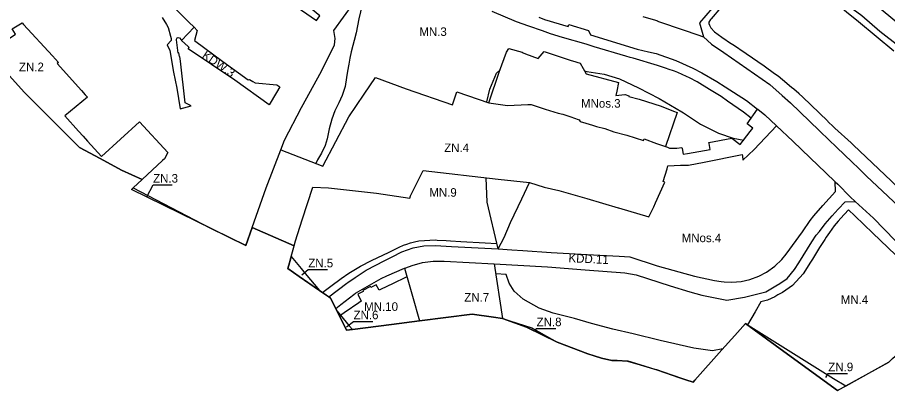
# Model space of a CAD drawing. Extents: x 7420436 to 7421695, y 5547261 to 5547909.
# Drawn here: x 7420752 to 7421258, y 5547294 to 5547511 of the extents above; entities that cross this region are included whole.
import ezdxf

# ---------------------------------------------------------------- set-up
doc = ezdxf.new("R2010")
doc.units = 0
for name, color, linetype in [('LIN_Granica Planu', 7, 'Continuous'), ('LIN_linie_rozgraniczajace', 7, 'Continuous'), ('LIN_nieprzekraczalna linia zabudowy', 7, 'Continuous'), ('TXT_Oznaczenia_przeznaczen', 7, 'Continuous')]:
    doc.layers.add(name, color=color, linetype=linetype)

msp = doc.modelspace()

# ---------------------------------------------------------------- linework, layer by layer
at = {"layer": 'LIN_Granica Planu'}
msp.add_lwpolyline([(7421259.05, 5547310.22), (7421233.98, 5547296.24), (7421229.23, 5547293.56), (7421198, 5547316.43), (7421175.73, 5547332.73), (7421175.66, 5547332.65), (7421169.4, 5547325.72), (7421161.85, 5547317.24), (7421146.1, 5547299.57), (7421145.17, 5547298.52), (7421140.86, 5547299.92), (7421136.27, 5547301.4), (7421135.97, 5547301.5), (7421132.96, 5547302.49), (7421124.07, 5547305.62), (7421123.66, 5547305.75), (7421114.38, 5547308.61), (7421107.35, 5547310.66), (7421106.92, 5547310.78), (7421100.9, 5547311.01), (7421097.82, 5547311.2), (7421091.82, 5547312.48), (7421087.65, 5547313.76), (7421083.89, 5547314.92), (7421066.03, 5547321.79), (7421048.25, 5547330.61), (7421034.16, 5547335.53), (7421028.95, 5547336.31), (7421016.64, 5547338.14), (7420985.93, 5547334.23), (7420969.62, 5547332.15), (7420946.83, 5547329.24), (7420943.45, 5547328.81), (7420934.09, 5547347.5), (7420915.94, 5547360.1), (7420909.33, 5547364.68), (7420910.25, 5547368.04), (7420910.46, 5547368.84), (7420912.94, 5547377.91), (7420888.52, 5547388.6), (7420884.81, 5547378.13), (7420818.18, 5547410.75), (7420818.2, 5547410.77), (7420819.17, 5547411.67), (7420824.52, 5547416.62), (7420812.48, 5547421.89), (7420799.97, 5547428.69), (7420788.05, 5547435.17), (7420777.16, 5547446), (7420755.7, 5547467.33), (7420734.75, 5547490.49)], dxfattribs=at)
at = {"layer": 'LIN_linie_rozgraniczajace'}
for p, q in [((7420847.46, 5547497.47), (7420854.67, 5547505.22)), ((7420841.44, 5547497.57), (7420838.99, 5547495.05))]:
    msp.add_line(p, q, dxfattribs=at)
for points in [[(7420787.58, 5547570.94), (7420802.56, 5547555.9), (7420812.54, 5547546.41), (7420823.13, 5547536.3), (7420842.51, 5547517.12), (7420845.49, 5547514.43), (7420851.66, 5547508.17), (7420854.67, 5547505.22), (7420856.54, 5547503.41), (7420855, 5547497.57)], [(7421190.81, 5547554.87), (7421207.78, 5547540.57), (7421229.97, 5547522.26), (7421236.25, 5547517.3), (7421243.31, 5547512.03), (7421253.86, 5547503.01), (7421265.16, 5547494.28), (7421275.34, 5547485.4), (7421281.23, 5547492.23), (7421278.94, 5547493.96), (7421270.78, 5547500.63), (7421271.58, 5547501.53), (7421250.27, 5547519.26), (7421237.97, 5547529.35), (7421228.01, 5547538.07), (7421207.81, 5547554.72), (7421197.34, 5547562.82)], [(7420898.71, 5547553.16), (7420881.83, 5547531.98), (7420878.15, 5547527.69), (7420880.42, 5547525.69), (7420882.59, 5547523.78), (7420890.6, 5547533.64), (7420911.68, 5547519.04), (7420925.95, 5547509.07), (7420927.93, 5547511.91), (7420922.47, 5547516.42), (7420897.75, 5547533.39), (7420908.28, 5547548.05)], [(7421190.81, 5547554.87), (7421189.2, 5547554.66), (7421179.25, 5547543.26), (7421170.41, 5547532.52), (7421158.61, 5547518.98), (7421156.23, 5547516.25), (7421148.93, 5547507.87), (7421151.31, 5547499.61)], [(7420905.23, 5547433.9), (7420907.37, 5547439.48), (7420917.18, 5547458.56), (7420928.84, 5547479.65), (7420936.4, 5547494.95), (7420936.88, 5547498.7), (7420936.09, 5547503.36), (7420952.92, 5547526.84), (7420943.47, 5547533.91), (7420933.81, 5547540.07), (7420930.16, 5547533.19), (7420908.28, 5547548.05)], [(7420734.75, 5547490.49), (7420750.75, 5547501.15), (7420748.84, 5547504.29), (7420754.54, 5547507.89), (7420755.44, 5547506.92), (7420772.24, 5547488.5), (7420775.71, 5547484.7), (7420775.06, 5547484.17), (7420789.09, 5547468.39), (7420791.36, 5547465.83), (7420792.6, 5547464.43), (7420779.43, 5547453.65), (7420787.41, 5547444.79), (7420790.03, 5547441.87), (7420792.67, 5547438.95), (7420800.8, 5547429.93), (7420822.96, 5547450.1), (7420839.32, 5547432.31), (7420837.5, 5547428.63), (7420836.4, 5547427.61), (7420824.52, 5547416.62)], [(7420836.09, 5547510.97), (7420838.59, 5547506.92), (7420839.62, 5547505.05), (7420841.03, 5547500.09), (7420841.31, 5547498.74), (7420841.44, 5547497.57)], [(7421055.34, 5547511.13), (7421058.67, 5547509.73), (7421072.49, 5547505.61), (7421072.88, 5547506.9), (7421084.35, 5547503.33), (7421085.41, 5547500.84), (7421112.63, 5547492.54), (7421119.23, 5547490.86), (7421123.62, 5547489.88), (7421135.16, 5547485.78), (7421144.95, 5547481.45), (7421150.2, 5547478.72), (7421159.07, 5547473.63), (7421163.78, 5547470.48), (7421176.31, 5547462.58), (7421182.69, 5547457.56)], [(7421115.89, 5547511.41), (7421123.28, 5547509.27), (7421124.43, 5547508.88), (7421124.49, 5547508.85), (7421139.96, 5547503.52), (7421147.34, 5547500.98), (7421151.31, 5547499.61)], [(7420845.47, 5547490.14), (7420844.43, 5547497.96), (7420844.55, 5547498.3), (7420844.8, 5547499.05), (7420845.5, 5547499.28), (7420846.12, 5547499.05), (7420847.09, 5547497.82), (7420847.46, 5547497.47), (7420851.19, 5547493.93), (7420851.79, 5547493.49)], [(7420855, 5547497.57), (7420871.5, 5547485.33), (7420886.16, 5547474.68), (7420886.9, 5547474.71), (7420888.98, 5547473.57), (7420890.2, 5547472.84), (7420902.88, 5547471.78), (7420904.65, 5547470.6), (7420902.74, 5547467.23), (7420898.43, 5547460.04), (7420878.35, 5547474.33), (7420851.17, 5547492.71), (7420851.79, 5547493.49)], [(7421151.31, 5547499.61), (7421155.87, 5547495.39), (7421163.14, 5547490.46), (7421189.92, 5547471.9), (7421196.95, 5547465.55), (7421201.8, 5547461.13), (7421218.54, 5547445.14), (7421219.16, 5547444.55), (7421228.93, 5547435.23), (7421237.56, 5547426.86), (7421241.59, 5547422.91), (7421246.18, 5547418.57), (7421255.37, 5547409.72), (7421268.45, 5547397.44)], [(7420838.99, 5547495.05), (7420840.64, 5547491.67)], [(7420840.64, 5547491.67), (7420842.63, 5547479.06), (7420844.59, 5547469.77), (7420846.61, 5547457.69), (7420853.07, 5547459.53), (7420849.56, 5547461.17), (7420846.79, 5547485.39), (7420846.46, 5547488.19), (7420846.13, 5547488.18), (7420845.76, 5547490.24), (7420845.47, 5547490.14)], [(7421026.34, 5547461.24), (7421032.51, 5547479.61), (7421036.64, 5547490.66), (7421037.85, 5547492.93), (7421045.6, 5547490.7), (7421046.18, 5547490.38), (7421047.67, 5547489.82), (7421055.05, 5547487.05), (7421058.38, 5547491.19), (7421074.19, 5547485.92), (7421074.88, 5547485.71), (7421079.44, 5547484.34), (7421082.92, 5547478.08), (7421101.83, 5547472.98), (7421100.8, 5547467.97), (7421100.28, 5547465.47), (7421105.37, 5547465.98), (7421105.6, 5547465.98), (7421107.74, 5547465.26), (7421107.67, 5547464.98), (7421113.79, 5547463.33), (7421126.61, 5547459.23), (7421133.77, 5547456.35), (7421135.87, 5547455.51), (7421129.01, 5547435.73)], [(7420734.75, 5547490.49), (7420755.7, 5547467.33), (7420777.16, 5547446), (7420788.05, 5547435.17), (7420799.97, 5547428.69), (7420812.48, 5547421.89), (7420824.52, 5547416.62)], [(7420905.23, 5547433.9), (7420929.58, 5547424.28), (7420944.73, 5547453.06), (7420953.78, 5547466.23), (7420960.29, 5547475.9), (7420978.09, 5547469.36), (7421005.17, 5547460.06), (7421007.68, 5547467.61), (7421026.34, 5547461.24)], [(7421026.34, 5547461.24), (7421037.09, 5547459.62), (7421049.02, 5547460.21), (7421050.96, 5547460.24), (7421059.06, 5547457.58), (7421066.55, 5547455.21), (7421069.31, 5547454.51), (7421074.57, 5547452.91), (7421075.52, 5547452.53), (7421078.9, 5547451.2), (7421079.48, 5547450.34), (7421082.75, 5547449.36), (7421086.67, 5547448.17), (7421088.93, 5547447.42), (7421093.84, 5547446.17), (7421099.1, 5547444.27), (7421106.6, 5547442.36), (7421116.37, 5547439.24), (7421116.73, 5547440.17), (7421123.87, 5547437.48), (7421129.01, 5547435.73)], [(7421129.01, 5547435.73), (7421130.27, 5547435.3), (7421131.39, 5547434.76), (7421135.64, 5547434.7), (7421138.67, 5547435.25), (7421138.78, 5547434.69), (7421139.39, 5547431.28), (7421141.82, 5547431.72), (7421155.11, 5547434.11), (7421154.49, 5547437.52), (7421154.38, 5547438.13), (7421167.78, 5547440.58), (7421172.62, 5547436.87), (7421178.43, 5547444.44), (7421179.91, 5547446.37), (7421176.56, 5547448.96), (7421182.69, 5547457.56)], [(7421182.69, 5547457.56), (7421182.85, 5547457.43), (7421186.83, 5547454.26), (7421193.73, 5547447.75)], [(7421049.85, 5547414.7), (7421058.47, 5547412.06), (7421067.09, 5547410.04), (7421083.33, 5547405.39), (7421101.58, 5547400.1), (7421101.78, 5547399.97), (7421119.32, 5547394.78), (7421122.25, 5547400.66), (7421123.25, 5547402.9), (7421128.74, 5547415.05), (7421127.74, 5547415.47), (7421130.04, 5547422.84), (7421130.51, 5547424.49), (7421137.84, 5547424.94), (7421142.56, 5547424.94), (7421151.69, 5547426.7), (7421173.72, 5547431.04), (7421173.95, 5547430.37), (7421174.04, 5547427.85), (7421180.74, 5547434.1), (7421193.73, 5547447.75)], [(7421193.73, 5547447.75), (7421203.24, 5547438.78), (7421213.3, 5547429.18), (7421222.49, 5547420.38), (7421227.8, 5547415.25)], [(7420888.52, 5547388.6), (7420896.73, 5547411.77), (7420905.23, 5547433.9)], [(7420912.94, 5547377.91), (7420913.71, 5547380.74), (7420917.66, 5547393), (7420923.84, 5547412.16), (7420932.97, 5547411.71), (7420960.92, 5547408.53), (7420980.25, 5547405.76), (7420980.75, 5547407.07), (7420987.98, 5547421.73), (7421031.7, 5547416.76), (7421049.85, 5547414.7)], [(7420819.17, 5547411.67), (7420824.52, 5547416.62), (7420824.52, 5547416.62)], [(7420863.54, 5547388.54), (7420818.18, 5547410.75), (7420818.2, 5547410.77), (7420819.17, 5547411.67)], [(7420819.17, 5547411.67), (7420823.32, 5547409.5), (7420841.52, 5547400.02), (7420863.54, 5547388.54)], [(7421031.62, 5547376.06), (7421039.75, 5547375.66), (7421046.1, 5547375.1), (7421062.47, 5547373.97), (7421083.5, 5547372.79), (7421102.06, 5547371.84), (7421108.32, 5547371.47), (7421124.19, 5547366.31), (7421145.98, 5547360.16), (7421157.68, 5547357.77), (7421161.46, 5547357.15), (7421163.19, 5547356.98), (7421167.63, 5547356.78), (7421173.06, 5547357.21), (7421178.18, 5547358.32), (7421183.39, 5547360.21), (7421187.9, 5547362.56), (7421192.71, 5547365.98), (7421196.83, 5547369.93), (7421199.36, 5547373.02), (7421208.93, 5547385.98), (7421213.35, 5547392.65), (7421215.5, 5547395.36), (7421220.76, 5547401.44), (7421227.97, 5547409.46), (7421227.8, 5547415.25)], [(7421031.62, 5547376.06), (7421035.1, 5547382.72), (7421038.96, 5547391.57), (7421045.55, 5547405.3), (7421049.85, 5547414.7)], [(7421227.8, 5547415.25), (7421229.36, 5547413.75), (7421236.56, 5547406.48), (7421239.51, 5547403.78)], [(7421029.39, 5547367.44), (7421060.48, 5547365.63), (7421082.32, 5547363.96), (7421105.48, 5547362.23), (7421112.05, 5547360.97), (7421131.75, 5547354.54), (7421143.23, 5547351.05), (7421150.22, 5547349.24), (7421164.71, 5547346.28), (7421175.14, 5547348.01), (7421187.55, 5547351.19), (7421193.38, 5547354.55), (7421195.59, 5547356.04), (7421199.83, 5547358.89), (7421204.23, 5547364.15), (7421206.67, 5547367.91), (7421214.34, 5547380.25), (7421216.86, 5547384.1), (7421218.72, 5547386.25), (7421222.14, 5547390.72), (7421226.09, 5547395.45), (7421229.64, 5547399.33), (7421233.78, 5547403.61), (7421239.51, 5547403.78)], [(7421239.51, 5547403.78), (7421250.24, 5547393.96), (7421262.79, 5547380.95), (7421272.96, 5547370.8), (7421281.3, 5547364.35), (7421301.65, 5547351.04), (7421354.18, 5547318.83)], [(7420863.54, 5547388.54), (7420884.81, 5547378.13), (7420888.52, 5547388.6)], [(7420888.52, 5547388.6), (7420912.94, 5547377.91)], [(7420911.22, 5547371.6), (7420912.94, 5547377.91)], [(7420933.14, 5547348.16), (7420943.56, 5547356.16), (7420944.19, 5547356.59), (7420948.43, 5547359.44), (7420954.83, 5547363.75), (7420965.82, 5547369.35), (7420969.91, 5547371.43), (7420975.69, 5547374.37), (7420982.3, 5547376.68), (7420988.35, 5547377.97), (7420995.28, 5547378.13), (7421004.53, 5547377.57), (7421016.11, 5547376.9), (7421031.62, 5547376.06)], [(7420911.22, 5547371.6), (7420910.46, 5547368.84), (7420910.25, 5547368.04), (7420909.33, 5547364.68), (7420909.33, 5547364.68), (7420915.94, 5547360.1), (7420927.7, 5547351.94)], [(7420911.22, 5547371.6), (7420916.98, 5547364.68), (7420919.33, 5547361.86), (7420927.7, 5547351.94)], [(7420937.12, 5547341.45), (7420940.05, 5547343.76), (7420947.66, 5547349.57), (7420948.68, 5547350.31), (7420963.68, 5547358.93), (7420966.84, 5547360.44), (7420977.16, 5547364.81)], [(7420977.16, 5547364.81), (7420978.01, 5547365.17), (7420981.57, 5547366.52), (7420987.68, 5547368.15), (7420993.94, 5547369), (7421000.27, 5547369.05), (7421029.39, 5547367.44)], [(7420977.16, 5547364.81), (7420981.83, 5547348.5), (7420985.93, 5547334.23)], [(7421029.39, 5547367.44), (7421034.16, 5547335.53)], [(7420927.7, 5547351.94), (7420933.14, 5547348.16)], [(7420933.14, 5547348.16), (7420934.09, 5547347.5), (7420937.12, 5547341.45)], [(7420937.12, 5547341.45), (7420937.97, 5547339.75)], [(7420937.97, 5547339.75), (7420943.45, 5547328.81), (7420946.83, 5547329.24)], [(7420937.97, 5547339.75), (7420945.06, 5547331.34), (7420946.83, 5547329.24)], [(7420985.93, 5547334.23), (7421016.64, 5547338.14), (7421028.95, 5547336.31), (7421034.16, 5547335.53)], [(7421034.16, 5547335.53), (7421048.25, 5547330.61), (7421066.03, 5547321.79)], [(7421034.16, 5547335.53), (7421051.29, 5547330.1), (7421052.23, 5547329.57), (7421066.03, 5547321.79)], [(7420946.83, 5547329.24), (7420969.62, 5547332.15), (7420985.93, 5547334.23)], [(7421066.03, 5547321.79), (7421083.89, 5547314.92), (7421087.65, 5547313.76), (7421091.82, 5547312.48), (7421097.82, 5547311.2), (7421100.9, 5547311.01), (7421106.92, 5547310.78), (7421114.38, 5547308.61), (7421124.07, 5547305.62), (7421132.96, 5547302.49), (7421136.27, 5547301.4), (7421140.86, 5547299.92), (7421145.17, 5547298.52), (7421146.1, 5547299.57), (7421161.85, 5547317.24), (7421169.4, 5547325.72), (7421175.66, 5547332.65), (7421175.73, 5547332.73)], [(7421175.73, 5547332.73), (7421198, 5547316.43), (7421229.23, 5547293.56), (7421233.99, 5547296.25)], [(7421175.73, 5547332.73), (7421226.89, 5547300.7), (7421233.99, 5547296.25)], [(7421233.99, 5547296.25), (7421259.05, 5547310.22), (7421261.28, 5547312.34), (7421264.24, 5547314.85), (7421269.97, 5547319.79), (7421274.19, 5547323.24)]]:
    msp.add_lwpolyline(points, dxfattribs=at)
at = {"layer": 'LIN_nieprzekraczalna linia zabudowy'}
for p, q in [((7421262.02, 5547491.2), (7421241.36, 5547508.44)), ((7420950.59, 5547344.76), (7420942.59, 5547339.29))]:
    msp.add_line(p, q, dxfattribs=at)
for points in [[(7421241.39, 5547508.41), (7421234.49, 5547514.1), (7421215.64, 5547529.82), (7421190.65, 5547550.47)], [(7420952.46, 5547518.36), (7420950.61, 5547510.16), (7420949.02, 5547501.95), (7420947.96, 5547497.46), (7420947.17, 5547494.55), (7420946.13, 5547490.84), (7420945.38, 5547487.23), (7420944.75, 5547483.67), (7420944.01, 5547479.72), (7420943.47, 5547475.86), (7420942.67, 5547470.73), (7420940.82, 5547465.44), (7420938.97, 5547461.12), (7420936.57, 5547456.62), (7420934.79, 5547451.69), (7420933.24, 5547446.13), (7420932.09, 5547440.31), (7420931.03, 5547436.34), (7420928.77, 5547431.95), (7420926.47, 5547427.9), (7420925.49, 5547425.9)], [(7421161.32, 5547516.69), (7421155.7, 5547510.2), (7421155.29, 5547509.71), (7421154.39, 5547508.25), (7421154.34, 5547507.86), (7421154.39, 5547507.37), (7421154.67, 5547506.5), (7421155.57, 5547504.88), (7421157.64, 5547502.61), (7421161.89, 5547499.41), (7421167.55, 5547495.66)], [(7421147.59, 5547473.37), (7421147.5, 5547473.42), (7421143, 5547475.76), (7421141.36, 5547476.54), (7421136.2, 5547478.83), (7421134.38, 5547479.57), (7421130.66, 5547480.88), (7421129.63, 5547481.21), (7421124.39, 5547482.85), (7421110.22, 5547487.14), (7421108.46, 5547487.66), (7421105.92, 5547488.31), (7421087.65, 5547493.9), (7421082.9, 5547495.3), (7421069.23, 5547499.32), (7421062.23, 5547501.47), (7421057.52, 5547503.09), (7421049.56, 5547505.79), (7421042.38, 5547508.43), (7421028.27, 5547514.31)], [(7421167.55, 5547495.66), (7421168.08, 5547495.31), (7421176.07, 5547489.97), (7421186.6, 5547482.8), (7421192.61, 5547478.37), (7421194.6, 5547476.84)], [(7421025.02, 5547461.69), (7421026.93, 5547469.14), (7421030.71, 5547478.43), (7421032.79, 5547480.36)], [(7421081.96, 5547479.8), (7421083.29, 5547479.51), (7421093.45, 5547477.85), (7421102.35, 5547475.14), (7421113.34, 5547469.9), (7421125.38, 5547463.7), (7421138.59, 5547455.94)], [(7421194.6, 5547476.84), (7421197.27, 5547474.8), (7421202.52, 5547470.41), (7421203.77, 5547469.3), (7421206.65, 5547466.77)], [(7421178.91, 5547452.25), (7421174.43, 5547455.81), (7421165.29, 5547462.2), (7421161.48, 5547464.82), (7421154.69, 5547468.91), (7421147.59, 5547473.37)], [(7421206.65, 5547466.77), (7421206.81, 5547466.62), (7421209.01, 5547464.58), (7421223.31, 5547450.63), (7421223.59, 5547450.36)], [(7421138.59, 5547455.94), (7421139.52, 5547455.39), (7421149.56, 5547448.68), (7421159.93, 5547443.45), (7421168.51, 5547440.6), (7421174.65, 5547439.52)], [(7421223.59, 5547450.36), (7421226.84, 5547447.23), (7421227.75, 5547446.39), (7421237.16, 5547437.94), (7421238.42, 5547436.73), (7421260.57, 5547415.56), (7421261.43, 5547414.77), (7421269.18, 5547407.35), (7421270.03, 5547406.53), (7421273.58, 5547403.18), (7421282.94, 5547394.32), (7421285.64, 5547391.95)], [(7421031.71, 5547376.22), (7421025.2, 5547403.3), (7421024.78, 5547417.55)], [(7421233.17, 5547396.19), (7421232.87, 5547395.87), (7421229.65, 5547392.24), (7421227.38, 5547389.53), (7421225.96, 5547387.63), (7421224.52, 5547385.69), (7421222.6, 5547382.88), (7421221.77, 5547381.57), (7421218.77, 5547376.94), (7421214.68, 5547370.06), (7421213.51, 5547368.3), (7421209.32, 5547361.63), (7421203.06, 5547354.82), (7421197.16, 5547350.79), (7421194.55, 5547349.3), (7421192.75, 5547348.22), (7421188.46, 5547346.25), (7421184.59, 5547345.2)], [(7421298.12, 5547345.82), (7421288.29, 5547352.43), (7421283.25, 5547356.04), (7421276.89, 5547361.09), (7421272.57, 5547364.37), (7421268.63, 5547367.82), (7421263.01, 5547372.74), (7421249.79, 5547385.26), (7421239.28, 5547395.3), (7421235.55, 5547398.83), (7421233.33, 5547396.36), (7421233.17, 5547396.19)], [(7420968.24, 5547374.28), (7420974.16, 5547377.07), (7420976.53, 5547378.19), (7420978.61, 5547378.95), (7420980.74, 5547379.67), (7420983, 5547380.24), (7420985.5, 5547380.77), (7420995.14, 5547381.33), (7420996.16, 5547381.26), (7421001.45, 5547380.96), (7421003.95, 5547380.8), (7421009.99, 5547380.47), (7421024.18, 5547379.62), (7421031, 5547379.17)], [(7420940.28, 5547358.95), (7420944.7, 5547362.04), (7420951.52, 5547366.14), (7420958.04, 5547369.44), (7420968.22, 5547374.27)], [(7420978.61, 5547359.75), (7420969.82, 5547355.66), (7420967.62, 5547354.55), (7420962.36, 5547351.98), (7420960.72, 5547355.22), (7420957.61, 5547353.68), (7420957.31, 5547354.18), (7420952.86, 5547351.85), (7420953.12, 5547351.33), (7420949.94, 5547349.65), (7420952.02, 5547345.7), (7420950.5, 5547344.7)], [(7421046.26, 5547346.74), (7421041.08, 5547351.43), (7421038.01, 5547356.21), (7421036.34, 5547361.21), (7421030.27, 5547361.59)], [(7420929.53, 5547350.66), (7420931.14, 5547352.01), (7420934.34, 5547354.47), (7420940.28, 5547358.95)], [(7421156.52, 5547316.66), (7421145.67, 5547318.34), (7421125.97, 5547322.81), (7421110.24, 5547326.54), (7421098.54, 5547329.43), (7421086.12, 5547332.71), (7421076.08, 5547335.55), (7421063.66, 5547338.62), (7421055.63, 5547341.62), (7421046.26, 5547346.74)], [(7421184.59, 5547345.2), (7421181.25, 5547339.36), (7421176.83, 5547331.93)], [(7420942.81, 5547339.45), (7420940.01, 5547337.33)], [(7421162.42, 5547317.88), (7421156.52, 5547316.66)]]:
    msp.add_lwpolyline(points, dxfattribs=at)
at = {"layer": 'TXT_Oznaczenia_przeznaczen'}
for points in [[(7420827.26, 5547406.53), (7420830.84, 5547413.47), (7420841.88, 5547413.47)], [(7420917.45, 5547360.96), (7420921.15, 5547364.1), (7420932.29, 5547364.1)], [(7420943.41, 5547330.74), (7420947.52, 5547333.88), (7420958.73, 5547333.88)], [(7421052.81, 5547328.71), (7421054.09, 5547329.83), (7421065.34, 5547329.83)], [(7421222.44, 5547301.15), (7421223.87, 5547303.61), (7421235.08, 5547303.61)]]:
    msp.add_lwpolyline(points, dxfattribs=at)

# ---------------------------------------------------------------- texts
for s, p in [('MN.3', (7420985.81, 5547500.17)), ('ZN.2', (7420752.78, 5547479.64)), ('MNos.3', (7421079.93, 5547458.38)), ('ZN.4', (7421000.25, 5547432.5)), ('ZN.3', (7420830.84, 5547414.72)), ('MN.9', (7420991.6, 5547406.5)), ('MNos.4', (7421138.51, 5547380.03)), ('ZN.5', (7420921.15, 5547365.35)), ('ZN.7', (7421011.98, 5547345.43)), ('MN.10', (7420953.71, 5547340.02)), ('MN.4', (7421231.14, 5547344.06)), ('ZN.6', (7420947.52, 5547335.13)), ('ZN.8', (7421054.09, 5547331.08)), ('ZN.9', (7421223.87, 5547304.86))]:
    msp.add_text(s, height=5, dxfattribs=at).set_placement(p)
for s, rotation, p in [('KDW.3', 325.544, (7420858.91, 5547487.79)), ('KDD.11', 357.2559, (7421072.56, 5547368.39))]:
    msp.add_text(s, height=5, rotation=rotation, dxfattribs=at).set_placement(p)

doc.saveas('drawing.dxf')
